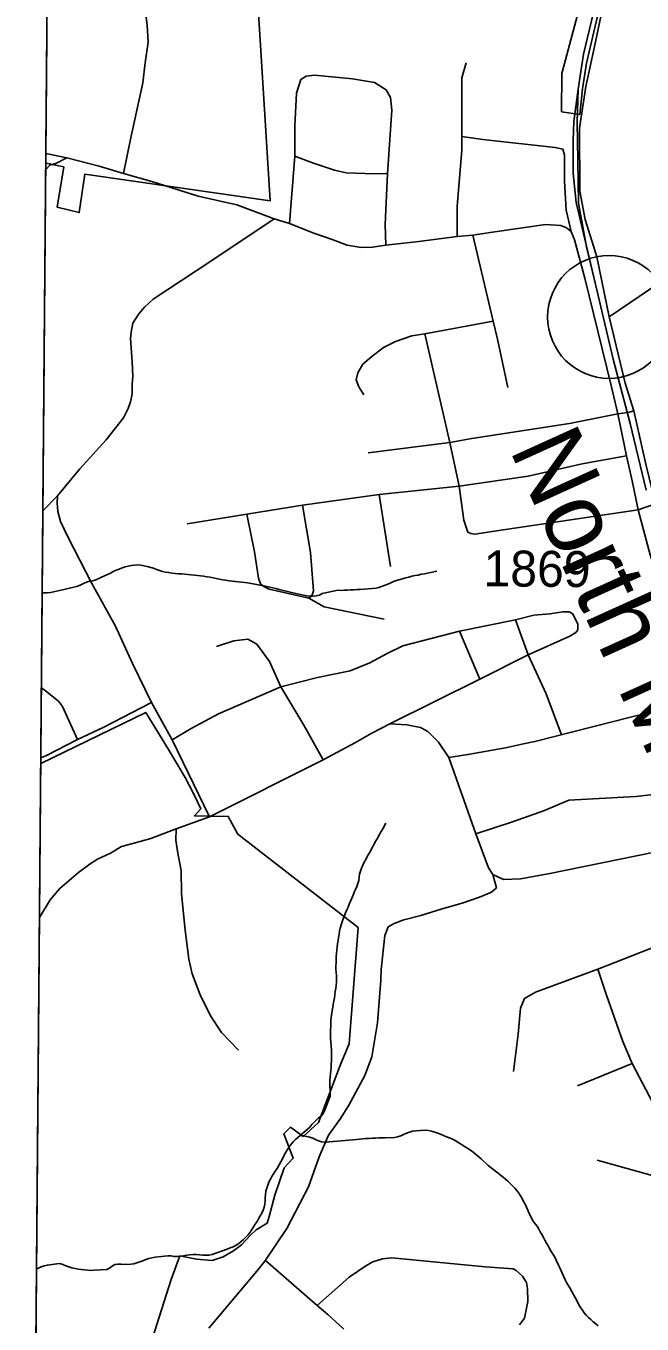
# Model space of a CAD drawing. Extents: x 1379453 to 1387082, y 594364 to 596664.
# Drawn here: x 1379988.7 to 1380115.2, y 596077 to 596343.6 of the extents above; entities that cross this region are included whole.
import ezdxf

# ---------------------------------------------------------------- set-up
doc = ezdxf.new("R2010")
doc.units = 0
for name, color, linetype in [('Old_Level_1', 7, 'Continuous'), ('Old_Level_11', 7, 'Continuous'), ('Old_Level_29', 7, 'Continuous'), ('Old_Level_32', 7, 'Continuous'), ('Old_Level_35', 7, 'Continuous'), ('Old_Level_44', 7, 'Continuous'), ('Old_Level_48', 7, 'Continuous'), ('Old_Level_49', 7, 'Continuous'), ('Old_Level_62', 7, 'Continuous'), ('Old_Level_8', 7, 'Continuous'), ('Sheet Clip Boundary CELL', 7, 'Continuous')]:
    doc.layers.add(name, color=color, linetype=linetype)

msp = doc.modelspace()

# ---------------------------------------------------------------- linework, layer by layer
at = {"layer": 'Old_Level_1'}
msp.add_line((1379993.85, 596441.11), (1379988.71, 595826.86), dxfattribs=at)
at = {"layer": 'Old_Level_29'}
for points in [[(1380107.34, 596348.11), (1380105.38, 596338.99), (1380103.71, 596331.15), (1380102.39, 596322.56), (1380102.49, 596309.63), (1380103.54, 596303.85), (1380105.93, 596296.15), (1380108.46, 596283.82)], [(1380108.46, 596283.82), (1380111.76, 596270.24), (1380113.55, 596264.52), (1380116.02, 596253.56), (1380117.97, 596245.42)]]:
    msp.add_lwpolyline(points, dxfattribs=at)
at = {"layer": 'Old_Level_32'}
msp.add_line((1380114.41, 596244.19), (1380117.97, 596245.42), dxfattribs=at)
for points in [[(1380007.19, 596357.36), (1380008.51, 596355.46), (1380009.64, 596353.87), (1380011.62, 596350.71), (1380012.55, 596348.48), (1380013.3, 596345.89), (1380013.57, 596343.76), (1380013.82, 596340.24), (1380013.22, 596335.99), (1380012.7, 596331.92), (1380010.13, 596320.01), (1380008.76, 596313.31)], [(1379997.08, 596316.51), (1379994.98, 596315.41), (1379993.64, 596314.99), (1379992.79, 596314.09)], [(1379997.08, 596316.51), (1379992.82, 596317.39)], [(1380008.76, 596313.31), (1380003.76, 596314.81), (1379997.08, 596316.51)], [(1380008.76, 596313.31), (1380014.56, 596311.62), (1380024.08, 596308.62), (1380031.99, 596306.83), (1380039.69, 596303.99)], [(1380026.39, 596181.13), (1380018.74, 596196.94), (1380014.49, 596204.66), (1380010.61, 596212.65), (1380007.1, 596220.33), (1380002.26, 596229.09), (1379997.28, 596238.66), (1379995.79, 596241.82), (1379995.23, 596243.86), (1379995.15, 596245.62), (1379995.16, 596247.1), (1379999.79, 596252.61), (1380005.18, 596258.58), (1380008.74, 596263.08), (1380009.71, 596265.02), (1380010.2, 596266.4), (1380010.5, 596268.06), (1380010.55, 596270.03), (1380010.63, 596271.56), (1380010.52, 596274.67), (1380010.17, 596279.41), (1380010.32, 596280.72), (1380010.67, 596282.51), (1380011.88, 596284.43), (1380013.03, 596285.8), (1380014.86, 596287.45), (1380026.65, 596295.31), (1380039.69, 596303.99)], [(1380039.69, 596303.99), (1380042.83, 596303.04), (1380047.86, 596301.05), (1380051.57, 596299.73), (1380054.71, 596298.59), (1380057.56, 596298.11), (1380059.85, 596298.18), (1380062.62, 596298.53), (1380069.41, 596299.29), (1380077.24, 596300.35), (1380080.5, 596300.65), (1380084.5, 596301.26), (1380095.39, 596302.78), (1380098.56, 596302.57), (1380099.7, 596302.13), (1380100.68, 596301.37), (1380101.39, 596299.64), (1380103.49, 596291.81), (1380108.92, 596269.72), (1380110.27, 596263.92), (1380112.03, 596255.3), (1380113.23, 596250.14), (1380114.41, 596244.19)], [(1380108.46, 596283.82), (1380118.87, 596290.87)], [(1380114.41, 596244.19), (1380116.9, 596234.95), (1380119.71, 596226.84), (1380120.31, 596224.99), (1380126.21, 596211.97), (1380129.39, 596205.72)], [(1380026.39, 596181.13), (1380049.77, 596192.89), (1380056.42, 596196.44), (1380059.77, 596198.34), (1380063.44, 596200.24), (1380066.91, 596200.02), (1380069.73, 596199.5), (1380071.26, 596198.68), (1380073.42, 596196.48), (1380075.56, 596193.36), (1380079.48, 596193.92), (1380087.21, 596195.33), (1380090.9, 596196.15), (1380093.23, 596196.62), (1380116.89, 596202.64), (1380129.39, 596205.72)], [(1379991.5, 596160.5), (1379993.71, 596164.1), (1379995.65, 596166.45), (1379999.5, 596169.72), (1380001.89, 596171.5), (1380003.37, 596172.49), (1380006.08, 596173.71), (1380008.36, 596175.07), (1380010.67, 596175.68), (1380014.32, 596176.69), (1380019.56, 596178.7), (1380026.39, 596181.13)], [(1380084.62, 596169.32), (1380085.34, 596166.57), (1380084.33, 596165.71), (1380081.89, 596164.67), (1380078.28, 596163.39), (1380074.2, 596162.25), (1380069.82, 596160.91), (1380066.35, 596160.01), (1380064.35, 596159.22), (1380063.13, 596158.54), (1380062.44, 596156.8), (1380061.68, 596149.78), (1380061.59, 596147.6), (1380060.88, 596138.83), (1380059.77, 596131.85), (1380058.28, 596128.05), (1380054.98, 596121.82), (1380053.18, 596119.01), (1380050.85, 596115.79), (1380048.9, 596111.35), (1380046.73, 596105.17), (1380042.31, 596096.58), (1380037.77, 596089.87), (1380036.13, 596087.87), (1380026.25, 596076.15)]]:
    msp.add_lwpolyline(points, dxfattribs=at)
msp.add_circle((1380108.46, 596283.82), 12.61, dxfattribs=at)
at = {"layer": 'Old_Level_35'}
for p, q in [((1380042.83, 596303.04), (1380043.93, 596316.85)), ((1380080.5, 596300.65), (1380084.65, 596282.92)), ((1380084.65, 596282.92), (1380070.65, 596280.36)), ((1380070.65, 596280.36), (1380075.76, 596258.03)), ((1380075.76, 596258.03), (1380058.97, 596255.89)), ((1380075.76, 596258.03), (1380077.65, 596249.04)), ((1380077.65, 596249.04), (1380061.28, 596247.33)), ((1380061.28, 596247.33), (1380045.53, 596245.15)), ((1380061.28, 596247.33), (1380063.59, 596232.6)), ((1380034.09, 596243.31), (1380021.8, 596241.32)), ((1380045.53, 596245.15), (1380034.09, 596243.31)), ((1380089.23, 596221.62), (1380077.75, 596219.31)), ((1380081.91, 596209.42), (1380077.75, 596219.31)), ((1380091.83, 596214.44), (1380089.23, 596221.62)), ((1380081.91, 596209.42), (1380091.83, 596214.44)), ((1380063.44, 596200.24), (1380081.91, 596209.42)), ((1380081.13, 596177.69), (1380075.56, 596193.36)), ((1380113.19, 596130.46), (1380102.01, 596125.9)), ((1380117.43, 596122.41), (1380113.19, 596130.46)), ((1380037.89, 596090.01), (1380048.54, 596080.76))]:
    msp.add_line(p, q, dxfattribs=at)
for points in [[(1380078.24, 596320.89), (1380078.26, 596332.96), (1380079.12, 596336.02)], [(1380062.94, 596313.23), (1380063.82, 596326.28), (1380063.57, 596328.92), (1380062.67, 596330.47), (1380060.31, 596331.98), (1380055.76, 596332.75), (1380047.94, 596333.46), (1380046.25, 596333.27), (1380045.19, 596332.58), (1380044.3, 596329.8), (1380043.95, 596323.09), (1380043.93, 596316.85)], [(1380077.24, 596300.35), (1380077.29, 596306.58), (1380078.23, 596318.01), (1380078.24, 596320.89)], [(1380078.24, 596320.89), (1380082.54, 596320.28), (1380097.38, 596318.65), (1380098.97, 596318.29), (1380099.33, 596317.07), (1380099.34, 596311.71), (1380099.68, 596305.78), (1380100.68, 596301.37)], [(1380043.93, 596316.85), (1380047.57, 596315.46), (1380052.09, 596313.96), (1380054.48, 596313.41), (1380058.32, 596313.3), (1380062.94, 596313.23)], [(1380062.94, 596313.23), (1380062.47, 596302.78), (1380062.62, 596298.53)], [(1380084.65, 596282.92), (1380085.58, 596279.29), (1380087.66, 596269.36)], [(1380070.65, 596280.36), (1380067.99, 596279.96), (1380064.59, 596278.77), (1380062.16, 596277.57), (1380059.77, 596275.73), (1380057.92, 596274.13), (1380056.9, 596272.36), (1380056.56, 596270.91), (1380057.04, 596269.44), (1380058.12, 596267.82)], [(1380110.27, 596263.92), (1380112.32, 596264.22), (1380113.55, 596264.52)], [(1380075.76, 596258.03), (1380080.27, 596258.87), (1380100.37, 596261.97), (1380110.27, 596263.92)], [(1380077.65, 596249.04), (1380091.85, 596251.1), (1380102.93, 596253.64), (1380112.03, 596255.3)], [(1380114.41, 596244.19), (1380085.8, 596239.97), (1380080.89, 596239.24), (1380080.1, 596239.34), (1380079.46, 596239.59), (1380078.66, 596242.1), (1380077.65, 596249.04)], [(1379995.16, 596247.1), (1379992.2, 596243.98)], [(1380046.82, 596226.08), (1380038.68, 596227.89), (1380037.53, 596228.46), (1380036.89, 596229.03), (1380036.45, 596230.15), (1380035.66, 596235.57), (1380034.09, 596243.31)], [(1380045.53, 596245.15), (1380047.16, 596235.42), (1380047.73, 596227.57), (1380047.4, 596226.51), (1380046.82, 596226.08)], [(1380046.82, 596226.08), (1380049.95, 596224.25), (1380062.25, 596221.78)], [(1380091.83, 596214.44), (1380100.43, 596218.23), (1380101.66, 596219.03), (1380102.05, 596219.58), (1380102.06, 596220.7), (1380101.05, 596222.83), (1380100.28, 596223.27), (1380099, 596223.28), (1380096.3, 596222.87), (1380093.02, 596222.58), (1380089.23, 596221.62)], [(1380077.75, 596219.31), (1380066.13, 596216.25), (1380062.87, 596214.71), (1380059.33, 596212.8), (1380055.31, 596211.12), (1380048.57, 596209.75), (1380041.08, 596207.86)], [(1380041.08, 596207.86), (1380038.74, 596213.08), (1380036.12, 596216.6), (1380034.31, 596217.62), (1380031.42, 596217.3), (1380027.86, 596216.12)], [(1380098.67, 596198.01), (1380095.55, 596206.39), (1380091.83, 596214.44)], [(1379999.28, 596197.02), (1379996.18, 596203.8), (1379995.38, 596204.91), (1379992.73, 596207.02), (1379991.9, 596207.66)], [(1380041.08, 596207.86), (1380028.26, 596202.34), (1380022.65, 596199.3), (1380018.74, 596196.94)], [(1380049.77, 596192.89), (1380045.78, 596199.96), (1380041.08, 596207.86)], [(1380014.49, 596204.66), (1380004.59, 596199.47), (1379999.28, 596197.02)], [(1379999.28, 596197.02), (1379992.76, 596193.69), (1379991.78, 596193.29)], [(1380081.13, 596177.69), (1380088.66, 596180.11), (1380095.22, 596182.48), (1380100.19, 596184.55), (1380113.97, 596185.32), (1380122.99, 596186.36), (1380127.57, 596187.25), (1380132.78, 596188.54), (1380136.89, 596189.9)], [(1380032.34, 596133.22), (1380028.9, 596136.86), (1380026.62, 596140.3), (1380024.48, 596144.61), (1380022.81, 596148.92), (1380022.19, 596151.91), (1380021.41, 596157.9), (1380020.67, 596165.37), (1380020.58, 596170.1), (1380019.91, 596173.72), (1380019.48, 596176.34), (1380019.56, 596178.7)], [(1380084.62, 596169.32), (1380083.73, 596170.69), (1380081.13, 596177.69)], [(1380121.52, 596174.65), (1380095.98, 596169.47), (1380090.26, 596168.4), (1380086.79, 596168.3), (1380084.62, 596169.32)], [(1380106.15, 596149.88), (1380120.16, 596155.31), (1380127.52, 596158.14)], [(1380106.15, 596149.88), (1380093.36, 596145.13), (1380091.08, 596143.83), (1380090.31, 596141.85), (1380089.83, 596136.5), (1380088.81, 596128.85)], [(1380113.19, 596130.46), (1380111.32, 596134.99), (1380107.91, 596144.54), (1380106.15, 596149.88)], [(1380127.21, 596104.73), (1380120.26, 596106.64), (1380106.05, 596110.65)], [(1380090.1, 596076.8), (1380091.08, 596078.18), (1380091.31, 596079.23), (1380091.78, 596081.6), (1380091.7, 596084.29), (1380091.51, 596085.51), (1380090.71, 596086.84), (1380089.38, 596088), (1380088.78, 596088.32), (1380083, 596088.73), (1380063.88, 596090.57), (1380061.93, 596090.36), (1380059.92, 596089.75), (1380058.49, 596088.94), (1380055.11, 596086.61), (1380048.54, 596080.76)], [(1380048.54, 596080.76), (1380050.68, 596078.92), (1380054, 596075.91)]]:
    msp.add_lwpolyline(points, dxfattribs=at)
at = {"layer": 'Old_Level_44'}
for points in [[(1380116.06, 596248.21), (1380112.78, 596261.93), (1380109.32, 596275.15), (1380106.26, 596288.21), (1380103.83, 596298.21), (1380102.17, 596307.22), (1380102.03, 596316.04), (1380101.94, 596323.8), (1380102.14, 596330.6), (1380103.22, 596337.78), (1380105.24, 596346.36), (1380107.03, 596355.59), (1380107.3, 596362.39), (1380107.51, 596369.43), (1380106.53, 596377.3), (1380104.36, 596387.78), (1380101.51, 596396.99), (1380098.46, 596405.32), (1380096.21, 596409.95), (1380082.73, 596438.92), (1380082.12, 596440.37)], [(1380116.06, 596248.21), (1380112.78, 596261.93), (1380109.32, 596275.15), (1380106.26, 596288.21), (1380101.73, 596307.35), (1380101.12, 596313.3), (1380101.11, 596320.14), (1380101.21, 596323.99), (1380102.14, 596330.6), (1380103.22, 596337.78), (1380105.24, 596346.36)]]:
    msp.add_lwpolyline(points, dxfattribs=at)
at = {"layer": 'Old_Level_48'}
for points in [[(1380035.36, 596363.85), (1380038.84, 596307.64), (1380000.8, 596313.17), (1379999.65, 596305.25), (1379995.12, 596306.35), (1379996.46, 596314.62), (1379992.8, 596315.39)], [(1380106.39, 596346.77), (1380103.8, 596335.92), (1380103.01, 596330.68), (1380102.43, 596325.43), (1380098.72, 596325.96), (1380098.79, 596333.84), (1380104.98, 596357.15)], [(1379991.77, 596192.11), (1380013.32, 596202.59), (1380017.98, 596194.98), (1380021.43, 596189.21), (1380023.18, 596185.84), (1380024.6, 596182.77), (1380023.32, 596181.37), (1380030.27, 596181.23), (1380032.23, 596177.59), (1380056.92, 596158.39), (1380055.1, 596134.54), (1380053.32, 596130.31), (1380048.78, 596118.35), (1380045.64, 596115.5), (1380043.03, 596117.4), (1380041.65, 596116.03), (1380043.6, 596111.02), (1380041.71, 596109.04), (1380039.79, 596103.43), (1380038.63, 596099.07), (1380038.24, 596097.7), (1380035.99, 596096.34), (1380034.85, 596095.23), (1380032.97, 596093.24), (1380031.33, 596092.01), (1380029.2, 596090.78), (1380026.95, 596090.04), (1380023.7, 596090.32), (1380020.33, 596090.98), (1380018.55, 596086.12), (1380006.81, 596049.35)]]:
    msp.add_lwpolyline(points, dxfattribs=at)
at = {"layer": 'Old_Level_49'}
for points in [[(1380035.36, 596363.85), (1380038.84, 596307.64), (1380000.8, 596313.17), (1379999.65, 596305.25), (1379995.12, 596306.35), (1379996.46, 596314.62), (1379992.8, 596315.39)], [(1380106.39, 596346.77), (1380103.8, 596335.92), (1380103.01, 596330.68), (1380102.43, 596325.43), (1380098.72, 596325.96), (1380098.79, 596333.84), (1380104.98, 596357.15)], [(1379991.77, 596192.11), (1380013.32, 596202.59), (1380017.98, 596194.98), (1380021.43, 596189.21), (1380023.18, 596185.84), (1380024.6, 596182.77), (1380023.32, 596181.37), (1380030.27, 596181.23), (1380032.23, 596177.59), (1380056.92, 596158.39), (1380055.1, 596134.54), (1380053.32, 596130.31), (1380048.78, 596118.35), (1380045.64, 596115.5), (1380043.03, 596117.4), (1380041.65, 596116.03), (1380043.6, 596111.02), (1380041.71, 596109.04), (1380039.79, 596103.43), (1380038.63, 596099.07), (1380038.24, 596097.7), (1380035.99, 596096.34), (1380034.85, 596095.23), (1380032.97, 596093.24), (1380031.33, 596092.01), (1380029.2, 596090.78), (1380026.95, 596090.04), (1380023.7, 596090.32), (1380020.33, 596090.98), (1380018.55, 596086.12), (1380006.81, 596049.35)]]:
    msp.add_lwpolyline(points, dxfattribs=at)
at = {"layer": 'Old_Level_62'}
for points in [[(1380003.06, 596229.86), (1380003.65, 596230.12), (1380004.25, 596230.39), (1380004.85, 596230.67), (1380005.44, 596230.95), (1380006.04, 596231.23), (1380006.63, 596231.51), (1380007.23, 596231.78), (1380007.84, 596232.03), (1380008.45, 596232.26), (1380009.08, 596232.47), (1380009.72, 596232.65), (1380010.37, 596232.79), (1380011.02, 596232.87), (1380011.67, 596232.88), (1380012.31, 596232.81), (1380012.96, 596232.69), (1380013.6, 596232.54), (1380014.88, 596232.2), (1380015.49, 596231.95), (1380016.11, 596231.73), (1380016.74, 596231.57), (1380017.38, 596231.42), (1380018.03, 596231.31), (1380018.68, 596231.23), (1380019.33, 596231.16), (1380019.99, 596231.09), (1380020.64, 596231.03), (1380021.3, 596230.97), (1380021.95, 596230.91), (1380022.6, 596230.85), (1380023.25, 596230.79), (1380023.91, 596230.72), (1380024.56, 596230.65), (1380025.21, 596230.56), (1380025.86, 596230.47), (1380026.51, 596230.36), (1380027.15, 596230.24), (1380027.8, 596230.11), (1380028.45, 596229.99), (1380029.09, 596229.86), (1380029.74, 596229.74), (1380030.38, 596229.63), (1380031.03, 596229.54), (1380031.68, 596229.46), (1380032.34, 596229.4), (1380032.99, 596229.35), (1380033.64, 596229.28), (1380034.29, 596229.19), (1380038.17, 596228.47), (1380040.05, 596228.05), (1380040.68, 596227.86), (1380043.23, 596227.23), (1380045.73, 596226.65), (1380046.37, 596226.52), (1380047.03, 596226.44), (1380047.68, 596226.46), (1380048.33, 596226.56), (1380048.97, 596226.71), (1380049.57, 596226.99), (1380050.2, 596227.14), (1380050.85, 596227.29), (1380051.49, 596227.43), (1380052.13, 596227.56), (1380052.78, 596227.68), (1380053.42, 596227.66), (1380054.07, 596227.68), (1380054.73, 596227.71), (1380055.38, 596227.74), (1380056.04, 596227.78), (1380056.7, 596227.82), (1380057.35, 596227.87), (1380060.62, 596228.1), (1380061.2, 596228.26), (1380063.02, 596228.93), (1380063.62, 596229.19), (1380064.22, 596229.47), (1380064.83, 596229.67), (1380066.7, 596230.25), (1380067.34, 596230.4), (1380067.97, 596230.55), (1380068.61, 596230.69), (1380069.26, 596230.82), (1380069.9, 596230.96), (1380070.54, 596231.09), (1380073.1, 596231.62)], [(1379992.06, 596227.18), (1379992.43, 596227.17), (1379993.09, 596227.17), (1379993.76, 596227.22), (1379994.39, 596227.33), (1379996.82, 596227.9), (1379999.35, 596228.56), (1379999.96, 596228.81), (1380000.55, 596229.08), (1380001.16, 596229.35), (1380001.78, 596229.55), (1380002.43, 596229.65), (1380003.06, 596229.86)], [(1380045.05, 596115.7), (1380046.04, 596116.56), (1380046.54, 596117), (1380047.02, 596117.44), (1380047.44, 596117.93), (1380048.82, 596119.33), (1380049.37, 596119.69), (1380049.74, 596120.2), (1380050, 596120.79), (1380051.17, 596123.77), (1380051.17, 596124.41), (1380051.16, 596125.06), (1380051.14, 596125.73), (1380051.12, 596126.39), (1380051.12, 596127.05), (1380051.16, 596127.71), (1380051.25, 596128.36), (1380051.33, 596129.01), (1380051.37, 596129.67), (1380051.41, 596130.32), (1380051.44, 596130.98), (1380051.46, 596131.64), (1380051.48, 596132.29), (1380051.49, 596132.95), (1380051.36, 596134.24), (1380051.26, 596135.54), (1380051.26, 596136.2), (1380051.34, 596139.48), (1380051.57, 596141.39), (1380051.72, 596142.03), (1380051.83, 596142.68), (1380051.95, 596143.32), (1380052.05, 596143.97), (1380052.14, 596144.62), (1380052.23, 596145.27), (1380052.32, 596145.92), (1380052.4, 596146.58), (1380052.46, 596147.23), (1380052.5, 596147.89), (1380052.47, 596148.54), (1380052.41, 596149.19), (1380052.38, 596149.85), (1380052.38, 596150.51), (1380052.39, 596151.16), (1380052.41, 596151.82), (1380052.44, 596152.48), (1380052.5, 596153.13), (1380052.57, 596153.78), (1380052.64, 596154.44), (1380052.72, 596155.09), (1380052.81, 596155.74), (1380052.9, 596156.39), (1380053.01, 596157.04), (1380053.12, 596157.68), (1380053.25, 596158.32), (1380053.42, 596158.96), (1380053.63, 596159.58), (1380053.86, 596160.2), (1380054.1, 596160.81), (1380054.35, 596161.42), (1380054.6, 596162.03), (1380054.85, 596162.63), (1380055.11, 596163.24), (1380055.37, 596163.84), (1380055.63, 596164.44), (1380055.89, 596165.05), (1380056.14, 596165.66), (1380056.38, 596166.26), (1380056.63, 596166.87), (1380056.86, 596167.48), (1380057.07, 596168.1), (1380057.13, 596168.76), (1380057.21, 596169.41), (1380057.65, 596170.62), (1380057.88, 596171.24), (1380058.18, 596171.82), (1380058.49, 596172.4), (1380058.81, 596172.98), (1380059.12, 596173.55), (1380059.44, 596174.13), (1380059.76, 596174.7), (1380060.07, 596175.28), (1380060.39, 596175.85), (1380060.71, 596176.42), (1380061.03, 596176.99), (1380061.35, 596177.57), (1380061.67, 596178.14), (1380061.99, 596178.71), (1380062.61, 596179.82)], [(1380037.85, 596102.92), (1380037.9, 596103.59), (1380037.99, 596104.24), (1380038.16, 596104.87), (1380038.38, 596105.49), (1380038.62, 596106.1), (1380038.9, 596106.71), (1380039.19, 596107.29), (1380039.53, 596107.86), (1380039.92, 596108.4), (1380040.31, 596108.92), (1380041.49, 596111.07), (1380041.77, 596111.67), (1380042.07, 596112.26), (1380042.4, 596112.83), (1380042.76, 596113.37), (1380043.17, 596113.89), (1380043.59, 596114.4), (1380044.05, 596114.86), (1380045.05, 596115.7)], [(1380045.05, 596115.7), (1380045.7, 596115.62), (1380046.35, 596115.53), (1380046.99, 596115.39), (1380047.61, 596115.17), (1380048.2, 596114.88), (1380048.79, 596114.6), (1380049.42, 596114.4), (1380050.07, 596114.3), (1380052.66, 596114.57), (1380056.58, 596114.88), (1380057.24, 596114.96), (1380057.89, 596115.02), (1380058.54, 596115.07), (1380059.2, 596115.11), (1380059.85, 596115.14), (1380060.51, 596115.17), (1380061.17, 596115.19), (1380061.82, 596115.21), (1380062.48, 596115.23), (1380064.39, 596115.31), (1380065.04, 596115.43), (1380065.67, 596115.63), (1380066.28, 596115.88), (1380066.88, 596116.15), (1380067.49, 596116.4), (1380068.11, 596116.59), (1380068.76, 596116.66), (1380070.72, 596116.8), (1380071.37, 596116.71), (1380072.01, 596116.58), (1380072.65, 596116.42), (1380073.27, 596116.2), (1380073.88, 596115.95), (1380074.49, 596115.7), (1380075.09, 596115.45), (1380075.7, 596115.19), (1380076.3, 596114.92), (1380076.89, 596114.65), (1380080.22, 596112.58), (1380082.21, 596110.92), (1380083.61, 596109.54), (1380085.15, 596108.35), (1380085.67, 596107.95), (1380086.19, 596107.55), (1380086.7, 596107.14), (1380087.21, 596106.72), (1380087.7, 596106.29), (1380088.18, 596105.84), (1380088.65, 596105.38), (1380089.09, 596104.89), (1380089.53, 596104.4), (1380089.93, 596103.88), (1380090.29, 596103.33), (1380090.61, 596102.77), (1380090.92, 596102.18), (1380091.21, 596101.59), (1380091.49, 596101), (1380091.76, 596100.4), (1380091.97, 596099.79), (1380092.9, 596098.1), (1380093.31, 596097.59), (1380093.68, 596097.05), (1380094.01, 596096.49), (1380094.34, 596095.92), (1380094.67, 596095.34), (1380094.99, 596094.77), (1380095.3, 596094.19), (1380095.62, 596093.61), (1380095.94, 596093.04), (1380096.25, 596092.47), (1380096.58, 596091.9), (1380097.23, 596090.84), (1380098.1, 596089.09), (1380098.38, 596088.5), (1380098.65, 596087.89), (1380098.91, 596087.29), (1380099.18, 596086.69), (1380099.45, 596086.09), (1380099.73, 596085.5), (1380100.41, 596084.4), (1380101.97, 596081.52), (1380102.28, 596080.95), (1380102.62, 596080.39), (1380102.98, 596079.83), (1380103.36, 596079.3), (1380103.78, 596078.8), (1380104.23, 596078.32), (1380104.72, 596077.88), (1380105.22, 596077.45), (1380105.72, 596077.04), (1380106.25, 596076.64)], [(1379990.9, 596088.29), (1379991.26, 596088.46), (1379991.86, 596088.73), (1379992.47, 596088.96), (1379993.12, 596089.1), (1379995.02, 596089.34), (1379995.68, 596089.38), (1379996.31, 596089.24), (1379996.92, 596088.96), (1379997.52, 596088.7), (1379998.16, 596088.54), (1379998.8, 596088.4), (1379999.44, 596088.27), (1380000.09, 596088.16), (1380000.75, 596088.08), (1380001.4, 596088.02), (1380002.05, 596088), (1380002.71, 596088.04), (1380005.32, 596088.2), (1380005.89, 596088.47), (1380006.41, 596088.89), (1380006.98, 596089.22), (1380007.6, 596089.31), (1380008.27, 596089.25), (1380008.94, 596089.19), (1380010.24, 596089.28), (1380010.87, 596089.36), (1380012.74, 596089.94), (1380013.33, 596090.24), (1380013.96, 596090.43), (1380014.59, 596090.58), (1380015.25, 596090.69), (1380016.52, 596090.86), (1380017.17, 596090.95), (1380017.83, 596091.01), (1380018.48, 596091.02), (1380019.13, 596090.88), (1380019.78, 596090.87), (1380020.43, 596090.93), (1380021.08, 596091.01), (1380021.74, 596091.1), (1380022.39, 596091.18), (1380023.04, 596091.24), (1380023.7, 596091.25), (1380024.36, 596091.21), (1380025.02, 596091.15), (1380025.68, 596091.11), (1380026.32, 596091.12), (1380026.96, 596091.24), (1380030.05, 596092.36), (1380030.67, 596092.6), (1380031.27, 596092.86), (1380031.86, 596093.16), (1380032.4, 596093.52), (1380032.92, 596093.92), (1380033.41, 596094.37), (1380033.88, 596094.83), (1380034.32, 596095.31), (1380034.73, 596095.83), (1380035.11, 596096.37), (1380035.46, 596096.92), (1380035.81, 596097.48), (1380036.16, 596098.04), (1380036.5, 596098.61), (1380036.83, 596099.19), (1380037.13, 596099.77), (1380037.4, 596100.36), (1380037.62, 596100.97), (1380037.76, 596101.6), (1380037.82, 596102.26), (1380037.85, 596102.92)]]:
    msp.add_lwpolyline(points, dxfattribs=at)
at = {"layer": 'Sheet Clip Boundary CELL'}
msp.add_lwpolyline([(1379993.85, 596441.11), (1380745.81, 596434.81), (1380742.6, 596052.18), (1380696.17, 596052.63), (1380694.49, 595820.94), (1379988.71, 595826.86)], close=True, dxfattribs=at)

# ---------------------------------------------------------------- texts
at = {"layer": 'Old_Level_11'}
msp.add_text('North Main St.', height=14.7638, rotation=294.3805, dxfattribs=at).set_placement((1380087.91, 596256.7))
at = {"layer": 'Old_Level_8'}
msp.add_text('1869', height=7.382, rotation=359.52, dxfattribs=at).set_placement((1380082.67, 596228.51))

doc.saveas('drawing.dxf')
